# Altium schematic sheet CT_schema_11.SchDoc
size 146 x 119 mm
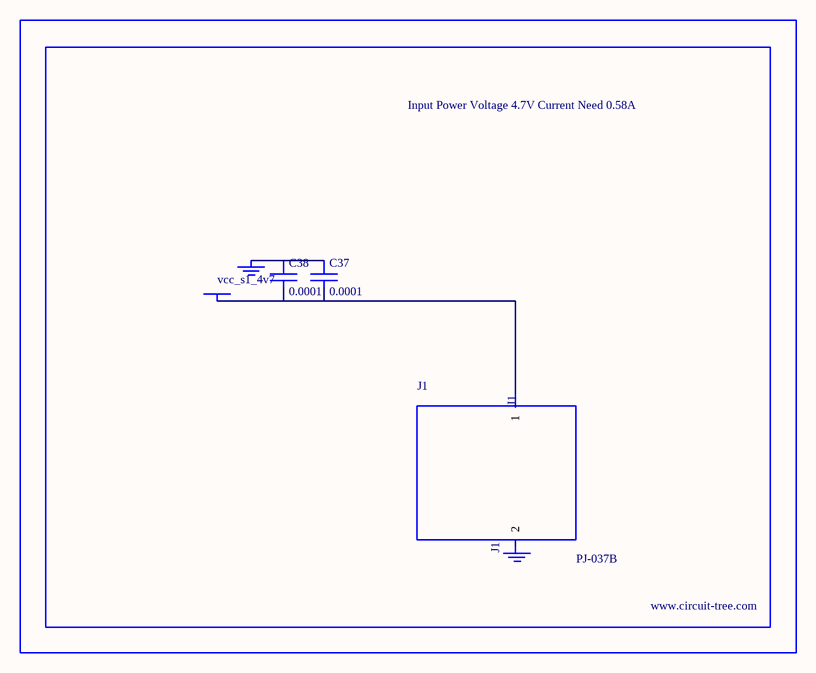
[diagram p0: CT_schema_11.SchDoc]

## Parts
BORDER10  (no value)
C37  0.0001  [EXV-9H]
C38  0.0001  [EXV-9H]
GND_INSTANCE_10_0  (no value)
GND_INSTANCE_10_1  (no value)
J1  PJ-037B  [PJ-037B_PACKAGE]
POWER_INSTANCE_10_0  vcc_s1_4v7

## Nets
NetC37_1: C37.1 C38.1 GND_INSTANCE_10_0.0(GND)
NetC37_2: C37.2 C38.2 J1.1 POWER_INSTANCE_10_0.0(PWR)

Not connected (* = marked no-connect by the designer): GND_INSTANCE_10_1 0(GND); J1 2

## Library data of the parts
BORDER10 = BORDER_PAGE10
C37 C38 = EDK107M035A9HAA
GND_INSTANCE_10_0 GND_INSTANCE_10_1 = GND
POWER_INSTANCE_10_0 = PWR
